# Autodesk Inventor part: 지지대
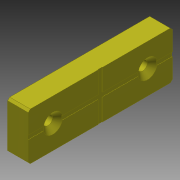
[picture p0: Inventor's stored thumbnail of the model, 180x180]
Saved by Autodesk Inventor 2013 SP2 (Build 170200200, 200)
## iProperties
Created: 2017-04
Part Number: 지지대
Material: 강철
Document SubType Name: Modeling
Designer: mduedu
Density: 7.85 g/cm^3
Mass: 97.8486 g
Surface Area: 48.4895 cm^2
Volume: 12.4648 cm^3
Author: mduedu
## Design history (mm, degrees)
sketch "스케치1"
  geometry: L1 (23, -35)-(23, 35); L2 (0, -35)-(0, 35); L3 (0, 35)-(23, 35); L4 (0, -35)-(23, -35); 2 further points
  constraints: 8 end point, 2 parallel, 1 coincident, 1 midpoint, 1 perpendicular, 1 vertical
  dimensions: "d1" = 23 distance between parallel lines of L2 L1; "d15" = 70 distance of L1.start L1.end
extrude "돌출1" new body sketch "스케치1" distance "d2" = 8; taper "d3" = 0 deg
chamfer "모따기2" distance "d16" = 1; stored, may be unused: second distance "d17" = 2, angle "d18" = 45 deg
sketch "스케치2"
  geometry: L1 (1, -35)-(22, -35) reference; L2 (23, -34)-(23, 34) reference; L3 (22, 35)-(1, 35) reference; L4 (0, 34)-(0, -34) reference; L5 (11.5, 35)-(11.5, -35); L6 (23, 0)-(0, 0); L7 (1, -35)-(0, -34) reference; L8 (23, -34)-(22, -35) reference; L9 (22, 35)-(23, 34) reference; L10 (0, 34)-(1, 35) reference; 2 further points
  constraints: 4 end point, 4 midpoint, 1 point on line, 1 symmetric about line
  dimensions: "d7" = 12 distance from line of point (11.5, 23) L3
  node "투영된 루프1"
sketch "스케치3"
  geometry: 4 further points
  constraints: 2 coincident
hole "구멍1" sketch "스케치3" at (11.5, 23), (11.5, -23) diameter "d8" = 4.5; stored, may be unused: countersink angle "d12" = 90 deg, drill point angle "d14" = 0 deg; dims "d9" = 6, "d10" = 9.4, "d11" = 2, "d13" = 8
sketch "스케치4"
  geometry: L1 (-35, 22)-(-35, 1) reference; L2 (35, 1)-(35, 22) reference; L3 (34, 23)-(-34, 23) reference; L4 (-34, 0)-(34, 0) reference; L5 (-35, 11.5)-(35, 11.5); L6 (0, 23)-(0, 0); L7 (-35, 12.5)-(35, 12.5); L8 (-35, 10.5)-(35, 10.5); L9 (-1, 23)-(-1, 0); L10 (1, 23)-(1, 0)
  constraints: 12 end point, 8 point on line, 4 parallel, 3 midpoint, 3 perpendicular
  dimensions: "d19" = 1 distance between parallel lines of L7 L5; "d21" = 1 distance between parallel lines of L8 L5; "d22" = 1 distance between parallel lines of L9 L6; "d23" = 1 distance between parallel lines of L10 L6
extrude "돌출2" cut sketch "스케치4" distance "d24" = 0.2; taper "d25" = 0 deg
extrude "돌출3" cut sketch "스케치4" distance "d26" = 0.2; taper "d27" = 0 deg
fillet "모깎기1" dims "d28" = 0.2
node "솔리드2"
node "솔리드1"
